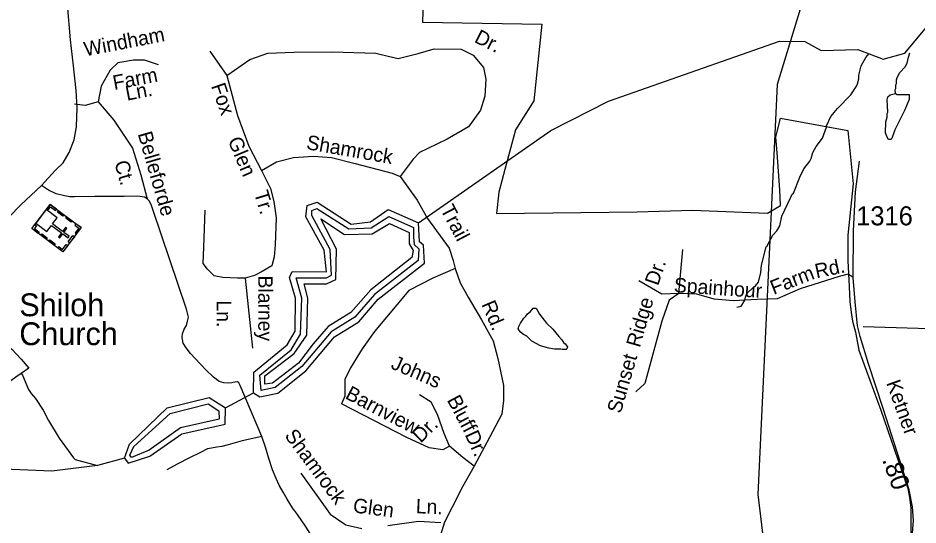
# Model space of a CAD drawing. Extents: x 1547597 to 1699558, y 810033 to 920809.
# Drawn here: x 1585242 to 1591150, y 858935 to 862265 of the extents above; entities that cross this region are included whole.
import ezdxf

# ---------------------------------------------------------------- set-up
doc = ezdxf.new("R2010")
doc.units = 0
for name, color, linetype in [('Exist Boundary Political City Limit New', 7, 'Continuous'), ('Exist Cultural Church with Cemetery CELL', 7, 'Continuous'), ('Exist Cultural Church with Cemetery Label', 7, 'Continuous'), ('Exist Hydrographic Buffer Line', 7, 'Continuous'), ('Exist Hydrographic Creek Single Shore', 7, 'Continuous'), ('Exist Hydrographic Lake Shore', 7, 'Continuous'), ('Exist Hydrographic Misc Water Feature', 7, 'Continuous'), ('Exist Road Non-System Type 51', 7, 'Continuous'), ('Exist Road Non-System Type 51 Label', 7, 'Continuous'), ('Exist Road Secondary Mileage Hundredths English Label', 7, 'Continuous'), ('Exist Road Secondary Type 51 Attributed', 7, 'Continuous'), ('Exist Road Secondary Type 51 Label', 7, 'Continuous'), ('Exist Road Secondary Type 51 Number Label', 7, 'Continuous'), ('Exist Utilities Electrical Transmission Line', 7, 'Continuous'), ('Map Preparation Boundary City Limit Buffer Line', 7, 'Continuous')]:
    doc.layers.add(name, color=color, linetype=linetype)

msp = doc.modelspace()

# ---------------------------------------------------------------- linework, layer by layer
at = {"layer": 'Exist Boundary Political City Limit New'}
msp.add_lwpolyline([(1587935.7, 863433.9), (1587898.2, 862237.9), (1588679.9, 862225), (1588629.2, 861721.8), (1588507, 861531.3), (1588437.9, 861269.4), (1588398.8, 861120.7), (1588382.7, 860980.4), (1589307, 860993.1), (1589669.8, 861003.2), (1590162.1, 860984.2), (1590248.6, 861033.1), (1590247.6, 861036.1), (1590242.4, 861136), (1590226.9, 861379.8), (1590216.2, 861482.8), (1590246.8, 861606.7), (1590690.6, 861525.5), (1590725.8, 861177), (1590689.2, 860837.9), (1590689.2, 860671.1), (1590697.6, 860501.6), (1590703.3, 860403.1), (1590711.7, 860332), (1590720.2, 860274.6), (1590739.9, 860200.8), (1590762.5, 860083.2), (1590906.2, 859689.4), (1591083.8, 859175.3), (1591095.1, 859115.2), (1591103.5, 859046.8), (1591099.3, 857935.2)], dxfattribs=at)
at = {"layer": 'Exist Cultural Church with Cemetery CELL'}
for points in [[(1585656.4, 860888.3), (1585537, 860729), (1585333.2, 860881.8), (1585452.7, 861041.1)], [(1585426.9, 861006.6), (1585359.6, 860916.9), (1585432, 860862.5), (1585462.5, 860903.1), (1585527.7, 860854.2), (1585507.9, 860827.9), (1585516.7, 860821.3), (1585536.5, 860847.7), (1585570.3, 860822.3), (1585577.2, 860831.6), (1585543.5, 860856.9), (1585563.3, 860883.4), (1585554.5, 860890), (1585534.7, 860863.5), (1585469.4, 860912.4), (1585499.3, 860952.3)], [(1585432.9, 861014.6), (1585442.1, 861007.7), (1585455.3, 861025.3), (1585487.6, 861001.1), (1585494.3, 861010), (1585452.8, 861041.1)], [(1585508.7, 860999.2), (1585543.3, 860973.2), (1585536.5, 860964.1), (1585501.8, 860990)], [(1585562.4, 860958.8), (1585597.1, 860932.8), (1585590.3, 860923.7), (1585555.6, 860949.7)], [(1585353.1, 860908.3), (1585362.3, 860901.4), (1585349.1, 860883.8), (1585381.4, 860859.6), (1585374.8, 860850.7), (1585333.2, 860881.8)], [(1585621.8, 860914.3), (1585614.9, 860905.2), (1585640.7, 860885.9), (1585616.4, 860853.5), (1585625.3, 860846.8), (1585656.4, 860888.3)], [(1585397.9, 860847.6), (1585432.5, 860821.6), (1585425.7, 860812.5), (1585391, 860838.5)], [(1585611.9, 860829.1), (1585580.8, 860787.6), (1585571.7, 860794.5), (1585602.8, 860835.9)], [(1585450.6, 860808), (1585485.3, 860782), (1585478.4, 860772.9), (1585443.8, 860798.9)], [(1585502.2, 860755), (1585509, 860764.1), (1585534.8, 860744.8), (1585559.1, 860777.2), (1585568, 860770.5), (1585536.9, 860729)]]:
    msp.add_lwpolyline(points, close=True, dxfattribs=at)
at = {"layer": 'Exist Hydrographic Buffer Line'}
msp.add_line((1587838.1, 860889.3), (1587838.1, 860826.7), dxfattribs=at)
for points in [[(1587838.1, 860826.7), (1587842.8, 860777.6), (1587873, 860749.7), (1587868.6, 860673.1), (1587581.9, 860449.1), (1587452.3, 860299.9), (1587298.5, 860204.7), (1587104.6, 859976.7), (1586929.2, 859837.9), (1586837.8, 859819.3), (1586830.2, 859919.3), (1587034.8, 860086.9), (1587096.4, 860188.9), (1587104.6, 860424.8), (1587067, 860558.1), (1587266.3, 860558.5), (1587300.8, 860575.2), (1587292.3, 860744), (1587171.8, 860967.2), (1587170.5, 861001), (1587203.1, 861014.9), (1587414.8, 860880), (1587561, 860887.8), (1587676.9, 860961.7), (1587838.1, 860889.3)], [(1587180.5, 860126.2), (1587082.7, 859998.9), (1586913.4, 859867.2), (1586863.2, 859859.3), (1586863.2, 859914.2), (1587054.5, 860061.6), (1587138, 860182), (1587144.5, 860424.2), (1587120.2, 860519.3), (1587266.1, 860518.5), (1587327.9, 860547), (1587332.1, 860747.8), (1587229.8, 860945.3), (1587385.8, 860843.4), (1587566.3, 860848.2), (1587681.2, 860916.2), (1587810.2, 860856.7), (1587810.2, 860782.3), (1587835.8, 860738.1), (1587827.6, 860691.8), (1587557.3, 860480.7), (1587426, 860330.7), (1587277.4, 860238.6), (1587180.5, 860126.2)], [(1586002.4, 859450.4), (1586240.8, 859667.6), (1586489.7, 859730.7), (1586559.5, 859685.3), (1586562.9, 859629.7), (1586309, 859573.5), (1586103.3, 859426.3), (1585985.9, 859378.1), (1585975.3, 859393.2), (1586002.4, 859450.4)]]:
    msp.add_lwpolyline(points, dxfattribs=at)
at = {"layer": 'Exist Hydrographic Creek Single Shore'}
msp.add_line((1586603.5, 859705.9), (1586788.6, 859803.9), dxfattribs=at)
for points in [[(1587871.6, 860921), (1588739.5, 861527.1), (1589117.6, 861719.8), (1590240.5, 862113.9), (1590406.6, 862110.5), (1590514.6, 862052.5), (1590756.5, 862057.5), (1590922.5, 861995.1), (1591064.6, 862034.8), (1591454.5, 862502.9), (1591543.6, 862845.7)], [(1585940.6, 859374.6), (1585764.5, 859325.7), (1585463.5, 859289.1), (1584255.6, 859339.9), (1583599.5, 859533.7), (1583174.5, 859516), (1582931.5, 859435.6)]]:
    msp.add_lwpolyline(points, dxfattribs=at)
at = {"layer": 'Exist Hydrographic Lake Shore'}
for points in [[(1586788.6, 859803.9), (1586790.5, 859938.5), (1587009.5, 860117.8), (1587061.6, 860208.8), (1587064.6, 860425.3), (1587024.6, 860560.6), (1587041.5, 860599.7), (1587266.6, 860598.5), (1587252.5, 860740), (1587130.6, 860959.1), (1587139.5, 861034.4), (1587206.6, 861056), (1587429.6, 860910.4), (1587555.6, 860927.5), (1587672.6, 861007.1), (1587871.6, 860921)], [(1586788.6, 859803.9), (1586829.6, 859776.8), (1586946.6, 859800.7), (1587132.5, 859947.9), (1587319.6, 860170.6), (1587478.6, 860269.2), (1587606.5, 860417.6), (1587909.6, 860654.3), (1587903.5, 860772.7), (1587878.5, 860796.1), (1587871.6, 860921)], [(1585940.6, 859374.6), (1585974.5, 859465.8), (1586220.6, 859703.8), (1586496.6, 859773.7), (1586603.5, 859705.9)], [(1585940.6, 859374.6), (1585964.6, 859341.3), (1586107.6, 859387.6), (1586317.6, 859534.4), (1586602.6, 859597.6), (1586603.5, 859705.9)]]:
    msp.add_lwpolyline(points, dxfattribs=at)
at = {"layer": 'Exist Hydrographic Misc Water Feature'}
for points in [[(1589960.6, 860366), (1589988.7, 860373.7), (1589994.8, 860379.7), (1590013.1, 860411.4), (1590019.5, 860441.3), (1590029.7, 860457.2), (1590068.2, 860494.7), (1590084.3, 860506.5), (1590102.5, 860530.2), (1590119.3, 860594), (1590123.8, 860641.9), (1590153.3, 860761.5), (1590158.3, 860764.8), (1590198.2, 860838.9), (1590224.5, 860868.5), (1590242.9, 860900.3), (1590255.7, 860964.1), (1590315.2, 861089.3), (1590325.4, 861109.1), (1590333.4, 861115.1), (1590373.6, 861221), (1590401.8, 861274.7), (1590439.9, 861325.6), (1590448.1, 861341.5), (1590460.5, 861381.4), (1590481.1, 861421), (1590523.7, 861476.5), (1590550.6, 861548.2), (1590550.7, 861556.2), (1590577.3, 861617.8), (1590622.9, 861670.8), (1590709.1, 861760.7), (1590745.7, 861817.6), (1590753.9, 861833.5), (1590762.3, 861865.4), (1590762.6, 861889.4), (1590777.2, 861951.1), (1590807.9, 862006.7), (1590828.9, 862031.2)], [(1591003.1, 861770.3), (1591001.4, 861794.3), (1591005.5, 861802.3), (1591005.8, 861826.3), (1591009.9, 861834.2), (1591010.2, 861858.2), (1591014.3, 861874.2), (1591030.7, 861907.9), (1591065.1, 861945.5), (1591079.5, 861969.3), (1591087.9, 862009.1), (1591097.7, 862037.4)], [(1591003.1, 861770.3), (1591013, 861762.2), (1591093.5, 861763.5), (1591092.6, 861729.2), (1591061.8, 861657.7), (1590998.3, 861530.5), (1590977.6, 861474.8), (1590971.5, 861466.9), (1590957.5, 861467.1), (1590947.7, 861483.2), (1590938, 861511.3), (1590938.9, 861583.2), (1590947.2, 861615.1), (1590947.5, 861639.1), (1590951.6, 861647), (1590948.7, 861731.1), (1590952.9, 861747), (1590967, 861760.8), (1591003.1, 861770.3)], [(1588644.2, 860359), (1588666, 860320.9), (1588712.2, 860261.1), (1588753.5, 860222.2), (1588793.2, 860174), (1588812.2, 860151.1), (1588824, 860134.8), (1588834, 860124.2), (1588848.4, 860106.3), (1588844.1, 860092.9), (1588839.7, 860088.5), (1588814.2, 860089), (1588805.3, 860089.8), (1588785.9, 860091), (1588763.2, 860090.5), (1588726.6, 860096), (1588672.9, 860111.7), (1588615.4, 860143.6), (1588582.4, 860175.1), (1588561, 860187.6), (1588551.1, 860194), (1588538, 860204), (1588525.5, 860224), (1588526.7, 860230.2), (1588530.5, 860239.6), (1588539.8, 860260.9), (1588563.4, 860292.9), (1588576.6, 860306.2), (1588587.2, 860322.5), (1588605.6, 860338.3), (1588624, 860359.3), (1588644.2, 860359)], [(1585064.7, 860121.3), (1585080.7, 860117.6), (1585088.7, 860125.5), (1585098.7, 860129.4), (1585122.8, 860133.1), (1585138.7, 860128.9), (1585178.5, 860108.4), (1585202.3, 860090.1), (1585263.5, 860025.3), (1585312.8, 859964.8), (1585262.8, 859930.7)], [(1585262.8, 859930.7), (1585228.1, 859905.9), (1585195.6, 859882.7), (1585180, 859898.5), (1585160.3, 859914.7), (1585144.5, 859936.9), (1585132.8, 859961), (1585125.2, 859997.1), (1585115.5, 860021.2), (1585085.9, 860059.6), (1585074.2, 860081.7), (1585070.4, 860097.7), (1585074.5, 860105.7), (1585064.7, 860121.3)], [(1585262.8, 859930.7), (1585270.3, 859919.3), (1585311.2, 859824.9), (1585328.8, 859798.6), (1585356.4, 859766.3), (1585407.5, 859689.7), (1585442.7, 859621.3), (1585511.3, 859506.5), (1585605.7, 859377.3), (1585617.6, 859365.2), (1585764.5, 859325.7)]]:
    msp.add_lwpolyline(points, dxfattribs=at)
at = {"layer": 'Exist Road Non-System Type 51'}
for p, q in [((1585896.2, 861970.4), (1585847.5, 861921.8)), ((1585999.5, 861988.7), (1585896.2, 861970.4)), ((1586072.4, 861988.7), (1585999.5, 861988.7)), ((1586163.5, 861958.3), (1586072.4, 861988.7)), ((1585847.5, 861921.8), (1585786.8, 861818.4)), ((1585786.8, 861818.4), (1585768.5, 861715)), ((1585768.5, 861715), (1585683.5, 861690.7)), ((1585768.5, 861715), (1585871.9, 861593.4)), ((1585683.5, 861690.7), (1585612.2, 861699.6)), ((1585871.9, 861593.4), (1585993.4, 861411)), ((1585993.4, 861411), (1586048.1, 861234.6)), ((1586048.1, 861234.6), (1586089.9, 861077.3)), ((1586733.4, 860557.2), (1586782.2, 860097.5)), ((1587099.5, 859274.9), (1587292.3, 859006.5)), ((1587292.3, 859006.5), (1587394.8, 858937.2)), ((1587394.8, 858937.2), (1587500.2, 858913.1)), ((1587669, 858931.2), (1587870.8, 858961.3)), ((1587870.8, 858961.3), (1588018.5, 858952.3))]:
    msp.add_line(p, q, dxfattribs=at)
for points in [[(1586501, 862047.8), (1586612, 861887.7)], [(1586612, 861887.7), (1586763.5, 861992.3), (1586882.9, 862035), (1587053.6, 862041.4), (1587305.4, 862043.6), (1587591.3, 862035), (1587672.4, 862013.7), (1587738.5, 861998.7), (1587868.7, 862032.9), (1587973.2, 862062.8), (1588150.3, 862060.6), (1588230.4, 862020.4), (1588298.6, 861939.3), (1588313.6, 861864.5), (1588307.2, 861751.3), (1588277.3, 861659.5), (1588200.5, 861550.6), (1588060, 861468.7), (1587932, 861408.9), (1587878.7, 861381.1), (1587836, 861338.4), (1587750.7, 861225.2)], [(1586612, 861887.7), (1586682.5, 861625.7), (1586757.2, 861422.8), (1586840.4, 861262.7)], [(1586840.4, 861262.7), (1586938.6, 861320.3), (1587049.5, 861348.1), (1587181.8, 861358.8), (1587299.2, 861350.2), (1587454.9, 861309.6), (1587698.1, 861245.6), (1587750.7, 861225.2)], [(1586840.4, 861262.7), (1586899.8, 861144.5), (1586921.2, 861061.2), (1586936.1, 860952.3), (1586929.7, 860775.1), (1586923.3, 860696), (1586908.4, 860638.4), (1586844.4, 860599.9), (1586795.3, 860574.3), (1586733.4, 860557.2)], [(1587750.7, 861225.2), (1587863.3, 861067.8), (1587929.5, 860948.2), (1588072.4, 860753.9), (1588098, 860672.7), (1588110.8, 860619.4)], [(1586843.7, 859515.8), (1586700.4, 859851.8), (1586692.7, 859868), (1586682.7, 859876.2), (1586664.9, 859874.4), (1586646.7, 859868.7), (1586622.7, 859867), (1586592.7, 859869.4), (1586562.7, 859877.9), (1586525.2, 859906.4), (1586475.8, 859955.3), (1586404.8, 860028.3), (1586373.3, 860062.8), (1586345.8, 860099.2), (1586326.2, 860129.4), (1586320.7, 860153.5), (1586318.8, 860169.6), (1586321.3, 860191.5), (1586333.7, 860221.5), (1586348, 860245.2), (1586354.4, 860273.1), (1586360.7, 860301), (1586347.6, 860353.3), (1586126.9, 861006.7), (1586117.2, 861032.9), (1586105.8, 861063.2), (1586089.9, 861077.3), (1586072.1, 861087.7), (1586028.2, 861096.2), (1585938.1, 861093.6), (1585746, 861092.3), (1585611.9, 861090.2), (1585581.9, 861090.6), (1585548, 861097.3), (1585492, 861110), (1585442.5, 861134.8), (1585396.6, 861165.3)], [(1586733.4, 860557.2), (1586682.2, 860557.2), (1586586.2, 860561.5), (1586528.6, 860572.2), (1586485.9, 860614.9), (1586458.2, 860653.3), (1586462.4, 860760.1), (1586471, 861003.6)], [(1589581.1, 860455.8), (1589605.6, 860744.5)], [(1588110.8, 860619.4), (1587966, 860556.1), (1587808.1, 860475), (1587582, 860205.9), (1587500.9, 860092.7), (1587424.7, 859968), (1587388.4, 859891.2), (1587388.4, 859782.3), (1587366.5, 859731.2)], [(1588110.8, 860619.4), (1588145, 860526.8), (1588196.2, 860430.7), (1588285.8, 860283.4), (1588360.4, 860144.6), (1588392, 860029.1), (1588428.7, 859852), (1588428.7, 859753.8), (1588418.2, 859662.6), (1588339.2, 859515.3), (1588237, 859321.2)], [(1589581.1, 860455.8), (1589468.7, 860450.9), (1589317.1, 860539)], [(1590724.4, 860561.1), (1590691.1, 860583), (1590632.4, 860568.4), (1590377.1, 860485.8), (1590226.3, 860421.1), (1590094.5, 860416.7), (1589939, 860406.7), (1589812.1, 860418.7), (1589698.5, 860450.9), (1589581.1, 860455.8)], [(1589581.1, 860455.8), (1589517.5, 860411.8), (1589468.7, 860274.7), (1589356.2, 859863.7), (1589297.5, 859809.9)], [(1590790, 860238.9), (1592383.9, 860191.8), (1592406.7, 860183.5), (1592432.7, 860181.1), (1592472.4, 860167.6)], [(1588074.8, 859453.6), (1588038.6, 859536.9), (1587995.9, 859660.8), (1587955.4, 859741.9), (1587878.6, 859791)], [(1588074.8, 859453.6), (1588030, 859428), (1587940.4, 859442.9), (1587795.3, 859509.1), (1587366.5, 859731.2)], [(1586843.7, 859515.8), (1586713.3, 859487.6), (1586620.7, 859462.8), (1586580.6, 859451.4), (1586546.5, 859445.9), (1586512.4, 859440.4), (1586486.3, 859434.7), (1586440, 859411.5), (1586367.4, 859376.5), (1586286.7, 859335.7), (1586218.1, 859296.7)], [(1587387.4, 858505.4), (1587240.7, 858745.5), (1587219.2, 858777.9), (1587199.7, 858816.2), (1587160.6, 858878.8), (1587129.3, 858927.2), (1587076.3, 859004.2), (1587043, 859048.7), (1587009.9, 859105.2), (1586982.4, 859151.5), (1586959, 859191.8), (1586937.8, 859240.3), (1586912.5, 859298.6), (1586889.6, 859372.9), (1586866.7, 859447.3), (1586843.7, 859515.8)], [(1588237, 859321.2), (1588162.3, 859378.9), (1588074.8, 859453.6)], [(1588237, 859321.2), (1588160.3, 859186), (1588092, 859051.5), (1588040.8, 858953.3)], [(1588040.8, 858953.3), (1588004.5, 858833.7), (1587972.5, 858667.1), (1587961.9, 858622.3)]]:
    msp.add_lwpolyline(points, dxfattribs=at)
at = {"layer": 'Exist Road Secondary Type 51 Attributed'}
for points in [[(1585113.2, 860889), (1585257.6, 861035.3), (1585396.6, 861165.3), (1585486.7, 861264), (1585538.1, 861313.7), (1585578.6, 861380.9), (1585611, 861464.3), (1585624.9, 861551.2), (1585630.7, 861675.1), (1585623.7, 861788.6), (1585607, 861950.2), (1585587.3, 862121.7), (1585565.9, 862353.9), (1585544.4, 862550.3), (1585520.1, 862781.9)], [(1591129.6, 857165.4), (1591114.3, 857528.3), (1591104.8, 857906.4), (1591114.3, 858108), (1591104.8, 858356.9), (1591098.5, 858539.7), (1591104.8, 858773.4), (1591120.5, 858965.6), (1591114.3, 859053.9), (1591092.2, 859167.3), (1591032.4, 859353.2), (1590922.2, 859699.8), (1590825.1, 859994), (1590771.6, 860173.6), (1590752.7, 860242.9), (1590737, 860400.4), (1590724.4, 860561.1), (1590727.5, 860868.5), (1590740.1, 861123.7), (1590765.3, 861325.3)]]:
    msp.add_lwpolyline(points, dxfattribs=at)
at = {"layer": 'Exist Utilities Electrical Transmission Line'}
msp.add_lwpolyline([(1595074.8, 882528.9), (1594795.4, 882224.2), (1594492.3, 881911.7), (1594314.2, 881725.8), (1594181.7, 881585.2), (1591756.7, 879036.3), (1591646.3, 875142), (1590597.3, 874408.7), (1590660.9, 873411.3), (1590633.8, 873059.7), (1590510, 871286.5), (1590671.8, 869193.1), (1591400.6, 867299.4), (1591680.4, 866599), (1590226.6, 861827.8), (1590099.7, 859136.4), (1590298, 857488.7)], dxfattribs=at)
at = {"layer": 'Map Preparation Boundary City Limit Buffer Line'}
msp.add_lwpolyline([(1587935.7, 863433.9), (1587898.2, 862237.9), (1588679.9, 862225), (1588629.2, 861721.8), (1588507, 861531.3), (1588437.9, 861269.4), (1588398.8, 861120.7), (1588382.7, 860980.4), (1589307, 860993.1), (1589669.8, 861003.2), (1590162.1, 860984.2), (1590248.6, 861033.1), (1590247.6, 861036.1), (1590242.4, 861136), (1590226.9, 861379.8), (1590216.2, 861482.8), (1590246.8, 861606.7), (1590690.6, 861525.5), (1590725.8, 861177), (1590689.2, 860837.9), (1590689.2, 860671.1), (1590697.6, 860501.6), (1590703.3, 860403.1), (1590711.7, 860332), (1590720.2, 860274.6), (1590739.9, 860200.8), (1590762.5, 860083.2), (1590906.2, 859689.4), (1591083.8, 859175.3), (1591095.1, 859115.2), (1591103.5, 859046.8), (1591099.3, 857935.2)], dxfattribs=at)

# ---------------------------------------------------------------- texts
at = {"layer": 'Exist Cultural Church with Cemetery Label'}
for s, p in [('Shiloh', (1585250.3, 860306.5)), ('Church', (1585250.3, 860116.5))]:
    msp.add_text(s, height=150, dxfattribs=at).set_placement(p)
at = {"layer": 'Exist Road Non-System Type 51 Label'}
for s, rotation, p in [('Dr.', 333.38876, (1588231.6, 862109.4)), ('Windham', 10.89302, (1585684.4, 862013)), ('Farm', 10.89302, (1585873.8, 861792.5)), ('Fox', 289.00166, (1586508.4, 861819.6)), ('Ln.', 10.89302, (1585956.9, 861722)), ('Belleforde', 286.13352, (1586027.1, 861505)), ('Glen', 292.86563, (1586617.6, 861461.8)), ('Shamrock', 350.00386, (1587130.5, 861404.7)), ('Ct.', 286.13352, (1585873.1, 861315.2)), ('Tr.', 286.95078, (1586790.1, 861116.4)), ('Trail', 297.73897, (1588012.7, 861008.5)), ('Dr.', 71.11651, (1589443.7, 860502.6)), ('Rd.', 12.0352, (1590484.3, 860554.6)), ('Farm', 21.38964, (1590202.8, 860446.5)), ('Blarney', 270, (1586819, 860573.7)), ('Spainhour', 356.13536, (1589545.7, 860465.1)), ('Ridge', 73.86115, (1589323.8, 860096.3)), ('Ln.', 270, (1586546.6, 860410.4)), ('Rd.', 292.91736, (1588283.1, 860385.4)), ('Sunset', 73.86115, (1589198.4, 859662.9)), ('Johns', 336.48461, (1587683.7, 859966.1)), ('Barnview', 332.15199, (1587383.8, 859769.9)), ('Bluff', 298.05587, (1588055.7, 859756.7)), ('Dr.', 44.24467, (1587885.5, 859469.7)), ('Shamrock', 306.55361, (1586987.7, 859521.8)), ('Dr.', 294.69324, (1588173.1, 859529.7)), ('Glen', 352.56344, (1587437.2, 859018.7)), ('Ln.', 357.66102, (1587852.2, 859012.7))]:
    msp.add_text(s, height=95, rotation=rotation, dxfattribs=at).set_placement(p)
at = {"layer": 'Exist Road Secondary Mileage Hundredths English Label'}
msp.add_text('.80', height=120, rotation=289.50441, dxfattribs=at).set_placement((1590914.1, 859364.4))
at = {"layer": 'Exist Road Secondary Type 51 Label'}
msp.add_text('Ketner', height=95, rotation=289.73818, dxfattribs=at).set_placement((1590940.6, 859868.7))
at = {"layer": 'Exist Road Secondary Type 51 Number Label'}
msp.add_text('1316', height=125, dxfattribs=at).set_placement((1590744.6, 860903.5))

doc.saveas('drawing.dxf')
